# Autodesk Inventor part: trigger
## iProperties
Created: 2010-11
Part Number: trigger
Document SubType Name: Modeling
Designer: ROBERT
Density: 1 g/cm^3
Author: ROBERT
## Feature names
1. Extrusion1
2. Chamfer2
3. Fillet5
4. Fillet8
5. Fillet9
6. Fillet10
7. Fillet11
